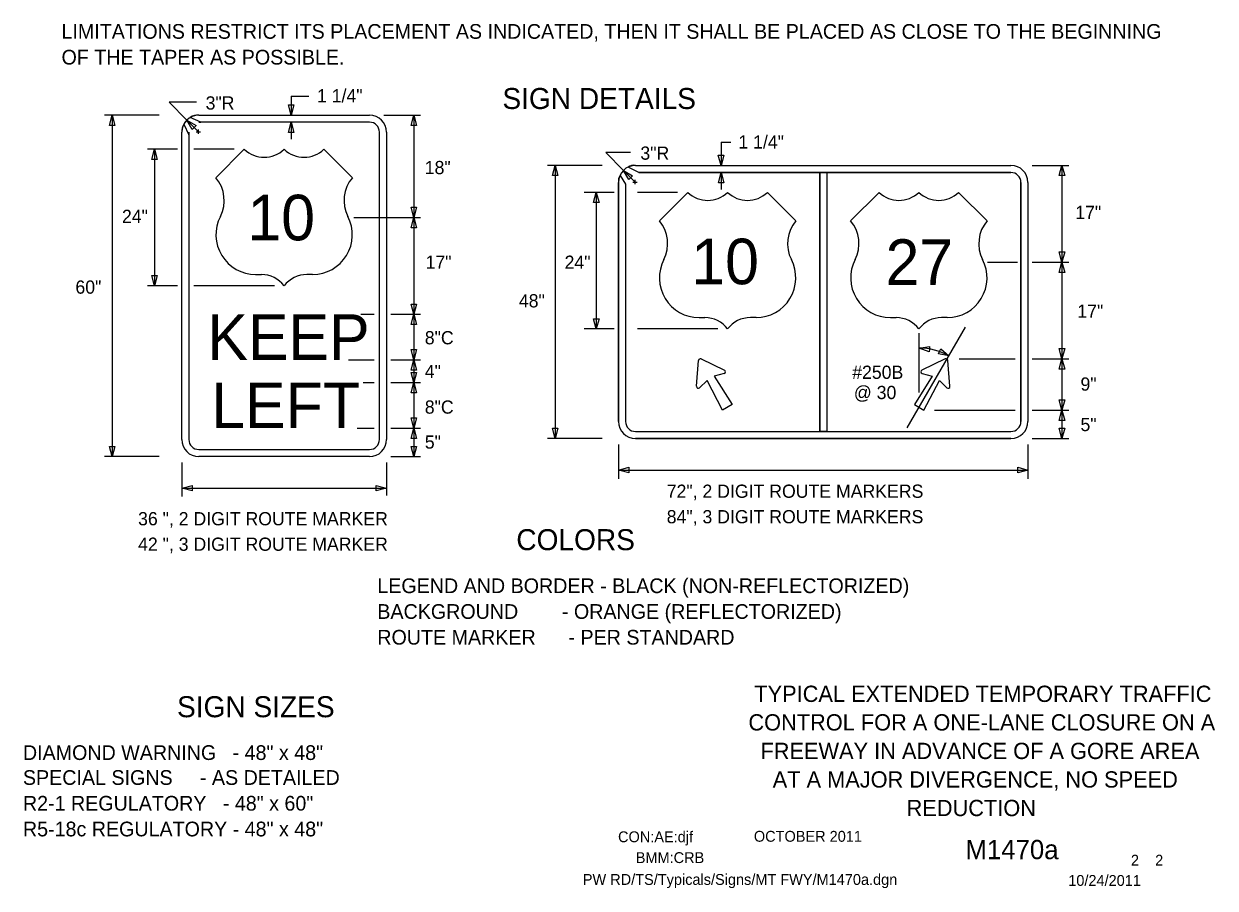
# Model space of a CAD drawing. Extents: x 16476 to 18475, y 6827 to 8243.
# Drawn here: x 17780 to 18461, y 7218 to 7712 of the extents above; entities that cross this region are included whole.
import ezdxf

# ---------------------------------------------------------------- set-up
doc = ezdxf.new("R2010")
doc.units = 0
for name, color, linetype in [('BORDER', 7, 'Continuous'), ('BORDER_SIGNAL_WO', 7, 'Continuous'), ('TRAFFIC_SIGNS_PR', 7, 'Continuous'), ('TYPICAL_EX', 7, 'Continuous'), ('TYPICAL_TEXT_DIMEN_PR', 7, 'Continuous')]:
    doc.layers.add(name, color=color, linetype=linetype)

msp = doc.modelspace()

# ---------------------------------------------------------------- linework, layer by layer
at = {"layer": 'BORDER'}
msp.add_line((17909.25, 7327.68), (17909.25, 7327.68), dxfattribs=at)
msp.add_line((17909.25, 7327.68), (17909.25, 7327.68), dxfattribs=at)
at = {"layer": 'TRAFFIC_SIGNS_PR'}
for p, q in [((17881.35, 7655.43), (17875.25, 7658.18)), ((17880.15, 7659.49), (17977.65, 7659.49)), ((17872.56, 7655.87), (17871.56, 7654.36)), ((17871.59, 7654.29), (17874.46, 7648.26)), ((17977.65, 7655.43), (17880.15, 7655.43)), ((17870.4, 7474.24), (17870.4, 7649.74)), ((17874.46, 7649.74), (17874.46, 7474.24)), ((17983.33, 7474.24), (17983.33, 7649.74)), ((17987.4, 7649.74), (17987.4, 7474.24)), ((18120.84, 7625.05), (18123.97, 7620.01)), ((18131.62, 7626.74), (18125.39, 7629.76)), ((18129.67, 7630.79), (18344.17, 7630.79)), ((18129.67, 7630.79), (18344.17, 7630.79)), ((18131.6, 7626.73), (18234.89, 7626.73)), ((18344.17, 7626.73), (18131.61, 7626.73)), ((18234.89, 7626.73), (18234.89, 7478.86)), ((18238.95, 7626.73), (18238.95, 7478.86)), ((18238.95, 7626.73), (18344.17, 7626.73)), ((18119.92, 7621.04), (18119.92, 7484.54)), ((18119.92, 7484.54), (18119.92, 7621.04)), ((18123.98, 7619.99), (18123.98, 7484.54)), ((18123.98, 7619.99), (18123.98, 7484.54)), ((18349.85, 7621.04), (18349.85, 7575.29)), ((18349.85, 7484.54), (18349.85, 7621.04)), ((18353.92, 7621.04), (18353.92, 7484.54)), ((18353.92, 7621.04), (18353.92, 7484.54)), ((18349.85, 7575.29), (18349.85, 7484.54)), ((18164.52, 7504.65), (18165.67, 7519.37)), ((18167.18, 7520.24), (18180.5, 7513.88)), ((18306.65, 7520.24), (18293.34, 7513.88)), ((18309.31, 7504.65), (18308.17, 7519.37)), ((18129.67, 7478.86), (18344.17, 7478.86)), ((18129.67, 7474.79), (18344.17, 7474.79)), ((18344.17, 7474.79), (18129.67, 7474.79)), ((17880.15, 7468.55), (17977.65, 7468.55)), ((17977.65, 7464.49), (17880.15, 7464.49))]:
    msp.add_line(p, q, dxfattribs=at)
for points in [[(18131.61, 7626.73), (18131.59, 7626.74)], [(18123.97, 7620.01), (18123.98, 7619.99)], [(18180.33, 7511.91), (18174.61, 7510.33), (18184.83, 7494.16), (18179.43, 7491.04), (18170.54, 7507.98), (18166.31, 7503.81)], [(18293.5, 7511.91), (18299.22, 7510.33), (18289.01, 7494.16), (18294.4, 7491.04), (18303.3, 7507.98), (18307.52, 7503.81)]]:
    msp.add_lwpolyline(points, dxfattribs=at)
msp.add_lwpolyline([(18234.89, 7626.73), (18238.95, 7626.73), (18238.95, 7478.86), (18234.89, 7478.86)], close=True, dxfattribs=at)
for centre, radius, start, end in [((17880.15, 7649.74), 9.75, 90, 180), ((17879.56, 7651.92), 7.6, 85.58319, 124.53531), ((17977.65, 7649.74), 9.75, 0, 90), ((17877.43, 7650.33), 7.06, 145.86811, 184.82317), ((17880.75, 7659.86), 4.47, 262.2432, 277.7568), ((17977.65, 7649.74), 5.69, 0, 90), ((17869, 7649), 5.51, 352.24294, 7.75653), ((18128.99, 7624.23), 6.6, 84.11162, 123.06374), ((18126.05, 7621.75), 6.17, 147.60925, 186.56283), ((18129.67, 7621.04), 9.75, 90, 180), ((18129.67, 7621.04), 9.75, 90, 180), ((18130.61, 7633.91), 7.24, 277.81035, 278.05403), ((18344.17, 7621.04), 9.75, 0, 90), ((18344.17, 7621.04), 9.75, 0, 90), ((18344.17, 7621.04), 5.69, 0, 89.99421), ((18344.17, 7621.04), 5.69, 0, 90), ((18166.73, 7519.28), 1.06, 64.48226, 175.51774), ((18307.11, 7519.28), 1.06, 4.48226, 115.51774), ((18180.04, 7512.92), 1.06, 285.9885, 64.48226), ((18293.79, 7512.92), 1.06, 115.51774, 254.0115), ((18165.57, 7504.57), 1.06, 175.51775, 314.01151), ((18308.26, 7504.57), 1.06, 225.98849, 4.48225), ((18129.67, 7484.54), 9.75, 180, 270), ((18129.67, 7484.54), 9.75, 180, 270), ((18129.67, 7484.54), 5.69, 180, 270), ((18129.67, 7484.54), 5.69, 180, 270), ((18344.17, 7484.54), 9.75, 270, 0), ((18344.17, 7484.54), 5.69, 270, 0), ((18344.17, 7484.54), 9.75, 270, 0), ((18344.17, 7484.54), 5.69, 270, 0), ((17880.15, 7474.24), 9.75, 180, 270), ((17880.15, 7474.24), 5.69, 180, 270), ((17977.65, 7474.24), 5.69, 270, 0), ((17977.65, 7474.24), 9.75, 270, 0)]:
    msp.add_arc(centre, radius, start, end, dxfattribs=at)
at = {"layer": 'TYPICAL_EX'}
for p, q in [((17889.9, 7623.74), (17906.15, 7639.99)), ((17967.9, 7623.74), (17951.65, 7639.99)), ((18143.28, 7599.13), (18159.53, 7615.38)), ((18221.28, 7599.13), (18205.03, 7615.38)), ((18252.56, 7599.13), (18268.81, 7615.38)), ((18330.56, 7599.13), (18314.31, 7615.38)), ((17912.62, 7568.45), (17915.87, 7568.45)), ((17945.17, 7568.45), (17941.92, 7568.45)), ((18166.01, 7543.84), (18169.26, 7543.84)), ((18198.55, 7543.84), (18195.3, 7543.84)), ((18275.28, 7543.84), (18278.53, 7543.84)), ((18307.83, 7543.84), (18304.58, 7543.84))]:
    msp.add_line(p, q, dxfattribs=at)
for centre, radius, start, end in [((17917.52, 7651.83), 16.42, 226.14041, 313.85958), ((17940.27, 7651.83), 16.42, 226.14042, 313.85959), ((17874.49, 7610.73), 20.16, 333.09768, 40.19361), ((17983.3, 7610.73), 20.16, 139.80639, 206.90233), ((18170.91, 7627.22), 16.42, 226.14041, 313.85958), ((18193.65, 7627.22), 16.42, 226.14042, 313.85959), ((18280.18, 7627.22), 16.42, 226.14041, 313.85958), ((18302.93, 7627.22), 16.42, 226.14042, 313.85959), ((17912.66, 7591.18), 22.73, 152.6698, 269.90132), ((17945.13, 7591.18), 22.73, 270.09868, 27.3302), ((18127.88, 7586.12), 20.16, 333.09768, 40.19361), ((18236.68, 7586.12), 20.16, 139.80639, 206.90233), ((18237.16, 7586.12), 20.16, 333.09768, 40.19361), ((18345.96, 7586.12), 20.16, 139.80639, 206.90233), ((18166.05, 7566.56), 22.73, 152.6698, 269.90132), ((18198.51, 7566.56), 22.73, 270.09868, 27.3302), ((18275.32, 7566.56), 22.73, 152.6698, 269.90132), ((18307.79, 7566.56), 22.73, 270.09868, 27.3302), ((17915.91, 7552.17), 16.28, 37.1038, 90.13853), ((17941.88, 7552.17), 16.28, 89.86147, 142.8962), ((18169.3, 7527.56), 16.28, 37.1038, 90.13853), ((18195.26, 7527.56), 16.28, 89.86147, 142.8962), ((18278.57, 7527.56), 16.28, 37.1038, 90.13853), ((18304.54, 7527.56), 16.28, 89.86147, 142.8962)]:
    msp.add_arc(centre, radius, start, end, dxfattribs=at)
at = {"layer": 'TYPICAL_TEXT_DIMEN_PR'}
for p, q in [((17878.76, 7666.78), (17863.11, 7666.78)), ((17863.11, 7666.78), (17873.35, 7656.54)), ((17932.87, 7659.49), (17931.3, 7665.35)), ((17931.3, 7665.35), (17932.87, 7665.35)), ((17932.87, 7670.25), (17932.87, 7659.49)), ((17932.87, 7670.25), (17942.97, 7670.25)), ((17932.87, 7665.35), (17934.44, 7665.35)), ((17934.44, 7665.35), (17932.87, 7659.49)), ((17857.57, 7659.49), (17826.27, 7659.49)), ((17829.04, 7653.63), (17830.61, 7659.49)), ((17830.61, 7659.49), (17830.61, 7464.49)), ((17830.61, 7659.49), (17832.18, 7653.63)), ((17985.94, 7659.49), (18006.9, 7659.49)), ((18001.43, 7653.63), (18003, 7659.49)), ((18003, 7659.49), (18003, 7600.99)), ((18003, 7659.49), (18004.57, 7653.63)), ((17830.61, 7653.63), (17829.04, 7653.63)), ((17832.18, 7653.63), (17830.61, 7653.63)), ((17873.35, 7656.54), (17879.9, 7649.98)), ((17876.38, 7651.28), (17873.35, 7656.54)), ((17873.35, 7656.54), (17878.6, 7653.51)), ((17877.49, 7652.39), (17876.38, 7651.28)), ((17878.6, 7653.51), (17877.49, 7652.39)), ((17931.35, 7649.57), (17932.92, 7655.43)), ((17932.92, 7655.43), (17932.92, 7645.68)), ((17932.92, 7655.43), (17934.49, 7649.57)), ((18003, 7653.63), (18001.43, 7653.63)), ((18004.57, 7653.63), (18003, 7653.63)), ((17878.7, 7649.98), (17881.11, 7649.98)), ((17879.9, 7648.77), (17879.9, 7651.19)), ((17932.92, 7649.57), (17931.35, 7649.57)), ((17934.49, 7649.57), (17932.92, 7649.57)), ((17868.02, 7639.99), (17850.9, 7639.99)), ((17853.22, 7634.13), (17854.79, 7639.99)), ((17854.79, 7639.99), (17854.79, 7561.99)), ((17854.79, 7639.99), (17856.36, 7634.13)), ((17900.26, 7639.99), (17877.39, 7639.99)), ((18126.81, 7638.08), (18112.63, 7638.08)), ((18112.63, 7638.08), (18122.78, 7627.93)), ((18178.53, 7643.94), (18178.53, 7630.79)), ((18178.53, 7643.94), (18184.05, 7643.94)), ((17854.79, 7634.13), (17853.22, 7634.13)), ((17856.36, 7634.13), (17854.79, 7634.13)), ((18178.53, 7630.79), (18176.95, 7636.65)), ((18176.95, 7636.65), (18178.53, 7636.65)), ((18178.53, 7636.65), (18180.1, 7636.65)), ((18180.1, 7636.65), (18178.53, 7630.79)), ((18110.69, 7630.79), (18079.39, 7630.79)), ((18082.16, 7624.93), (18083.73, 7630.79)), ((18083.73, 7624.93), (18082.16, 7624.93)), ((18083.73, 7630.79), (18083.73, 7474.79)), ((18083.73, 7630.79), (18085.3, 7624.93)), ((18085.3, 7624.93), (18083.73, 7624.93)), ((18122.78, 7627.93), (18129.43, 7621.28)), ((18125.81, 7622.67), (18122.78, 7627.93)), ((18122.78, 7627.93), (18128.04, 7624.9)), ((18128.04, 7624.9), (18126.93, 7623.78)), ((18177, 7620.87), (18178.57, 7626.73)), ((18177, 7620.87), (18178.57, 7626.73)), ((18178.57, 7626.73), (18178.57, 7616.98)), ((18178.57, 7626.73), (18180.15, 7620.87)), ((18178.57, 7626.73), (18180.15, 7620.87)), ((18356.29, 7630.79), (18377.25, 7630.79)), ((18371.78, 7624.93), (18373.35, 7630.79)), ((18373.35, 7624.93), (18371.78, 7624.93)), ((18373.35, 7630.79), (18373.35, 7575.54)), ((18373.35, 7630.79), (18374.92, 7624.93)), ((18374.92, 7624.93), (18373.35, 7624.93)), ((18126.93, 7623.78), (18125.81, 7622.67)), ((18128.22, 7621.28), (18130.64, 7621.28)), ((18129.43, 7620.07), (18129.43, 7622.49)), ((18178.57, 7620.87), (18177, 7620.87)), ((18178.57, 7620.87), (18177, 7620.87)), ((18180.15, 7620.87), (18178.57, 7620.87)), ((18180.15, 7620.87), (18178.57, 7620.87)), ((18117.55, 7615.38), (18100.42, 7615.38)), ((18105.71, 7609.52), (18107.28, 7615.38)), ((18107.28, 7615.38), (18107.28, 7537.38)), ((18107.28, 7615.38), (18108.86, 7609.52)), ((18153.65, 7615.38), (18130.77, 7615.38)), ((18003, 7600.99), (18001.43, 7606.85)), ((18001.43, 7606.85), (18003, 7606.85)), ((18003, 7606.85), (18004.57, 7606.85)), ((18004.57, 7606.85), (18003, 7600.99)), ((18107.28, 7609.52), (18105.71, 7609.52)), ((18108.86, 7609.52), (18107.28, 7609.52)), ((17968.79, 7600.99), (18006.9, 7600.99)), ((18001.43, 7595.13), (18003, 7600.99)), ((18003, 7600.99), (18003, 7545.74)), ((18003, 7600.99), (18004.57, 7595.13)), ((18003, 7595.13), (18001.43, 7595.13)), ((18004.57, 7595.13), (18003, 7595.13)), ((18373.35, 7575.54), (18371.78, 7581.4)), ((18371.78, 7581.4), (18373.35, 7581.4)), ((18373.35, 7581.4), (18374.92, 7581.4)), ((18374.92, 7581.4), (18373.35, 7575.54)), ((18330.73, 7575.54), (18347.88, 7575.54)), ((18356.29, 7575.54), (18377.25, 7575.54)), ((18371.78, 7569.68), (18373.35, 7575.54)), ((18373.35, 7569.68), (18371.78, 7569.68)), ((18373.35, 7575.54), (18373.35, 7520.29)), ((18373.35, 7575.54), (18374.92, 7569.68)), ((18374.92, 7569.68), (18373.35, 7569.68)), ((17854.79, 7561.99), (17853.22, 7567.85)), ((17853.22, 7567.85), (17854.79, 7567.85)), ((17854.79, 7567.85), (17856.36, 7567.85)), ((17856.36, 7567.85), (17854.79, 7561.99)), ((17868.02, 7561.99), (17850.9, 7561.99)), ((17923.39, 7561.99), (17877.39, 7561.99)), ((18003, 7545.74), (18001.43, 7551.6)), ((18001.43, 7551.6), (18003, 7551.6)), ((18003, 7551.6), (18004.57, 7551.6)), ((18004.57, 7551.6), (18003, 7545.74)), ((17972.72, 7545.74), (17980.4, 7545.74)), ((17989.77, 7545.74), (18006.9, 7545.74)), ((18001.43, 7539.88), (18003, 7545.74)), ((18003, 7545.74), (18003, 7519.74)), ((18003, 7545.74), (18004.57, 7539.88)), ((18107.28, 7537.38), (18105.71, 7543.24)), ((18105.71, 7543.24), (18107.28, 7543.24)), ((18107.28, 7543.24), (18108.86, 7543.24)), ((18108.86, 7543.24), (18107.28, 7537.38)), ((18003, 7539.88), (18001.43, 7539.88)), ((18004.57, 7539.88), (18003, 7539.88)), ((18117.55, 7537.38), (18100.42, 7537.38)), ((18176.77, 7537.38), (18130.77, 7537.38)), ((18284.95, 7480.89), (18318.19, 7538.48)), ((18291.71, 7501.05), (18291.71, 7535.04)), ((18003, 7519.74), (18001.43, 7525.6)), ((18001.43, 7525.6), (18003, 7525.6)), ((18003, 7525.6), (18004.57, 7525.6)), ((18004.57, 7525.6), (18003, 7519.74)), ((18291.74, 7526.49), (18297.73, 7527.45)), ((18297.4, 7524.32), (18291.74, 7526.49)), ((18297.57, 7525.88), (18297.4, 7524.32)), ((18297.73, 7527.45), (18297.57, 7525.88)), ((18302.72, 7523.16), (18303.4, 7524.58)), ((18308.69, 7522.03), (18302.72, 7523.16)), ((18303.4, 7524.58), (18304.09, 7525.99)), ((18304.09, 7525.99), (18308.69, 7522.03)), ((18373.35, 7520.29), (18371.78, 7526.15)), ((18371.78, 7526.15), (18373.35, 7526.15)), ((18373.35, 7526.15), (18374.92, 7526.15)), ((18374.92, 7526.15), (18373.35, 7520.29)), ((17965.71, 7519.74), (17980.4, 7519.74)), ((17989.77, 7519.74), (18006.9, 7519.74)), ((18001.43, 7513.88), (18003, 7519.74)), ((18003, 7519.74), (18003, 7506.74)), ((18003, 7519.74), (18004.57, 7513.88)), ((18314.66, 7520.29), (18346.53, 7520.29)), ((18356.29, 7520.29), (18377.25, 7520.29)), ((18371.78, 7514.43), (18373.35, 7520.29)), ((18373.35, 7520.29), (18373.35, 7491.04)), ((18373.35, 7520.29), (18374.92, 7514.43)), ((18003, 7513.88), (18001.43, 7513.88)), ((18003, 7506.74), (18001.43, 7512.6)), ((18001.43, 7512.6), (18003, 7512.6)), ((18004.57, 7513.88), (18003, 7513.88)), ((18003, 7512.6), (18004.57, 7512.6)), ((18004.57, 7512.6), (18003, 7506.74)), ((18373.35, 7514.43), (18371.78, 7514.43)), ((18374.92, 7514.43), (18373.35, 7514.43)), ((17974.06, 7506.74), (17980.4, 7506.74)), ((17989.77, 7506.74), (18006.9, 7506.74)), ((18001.43, 7500.88), (18003, 7506.74)), ((18003, 7506.74), (18003, 7480.74)), ((18003, 7506.74), (18004.57, 7500.88)), ((18003, 7500.88), (18001.43, 7500.88)), ((18004.57, 7500.88), (18003, 7500.88)), ((18373.35, 7491.04), (18371.78, 7496.9)), ((18371.78, 7496.9), (18373.35, 7496.9)), ((18373.35, 7496.9), (18374.92, 7496.9)), ((18374.92, 7496.9), (18373.35, 7491.04)), ((18300.52, 7491.04), (18346.53, 7491.04)), ((18356.29, 7491.04), (18377.25, 7491.04)), ((18371.78, 7485.18), (18373.35, 7491.04)), ((18373.35, 7491.04), (18373.35, 7474.79)), ((18373.35, 7491.04), (18374.92, 7485.18)), ((18003, 7480.74), (18001.43, 7486.6)), ((18001.43, 7486.6), (18003, 7486.6)), ((18003, 7486.6), (18004.57, 7486.6)), ((18004.57, 7486.6), (18003, 7480.74)), ((18373.35, 7485.18), (18371.78, 7485.18)), ((18374.92, 7485.18), (18373.35, 7485.18)), ((17970.56, 7480.74), (17980.4, 7480.74)), ((17989.77, 7480.74), (18006.9, 7480.74)), ((18001.43, 7474.88), (18003, 7480.74)), ((18003, 7474.88), (18001.43, 7474.88)), ((18003, 7480.74), (18003, 7464.49)), ((18003, 7480.74), (18004.57, 7474.88)), ((18004.57, 7474.88), (18003, 7474.88)), ((18110.69, 7474.79), (18079.39, 7474.79)), ((18083.73, 7474.79), (18082.16, 7480.65)), ((18082.16, 7480.65), (18083.73, 7480.65)), ((18083.73, 7480.65), (18085.3, 7480.65)), ((18085.3, 7480.65), (18083.73, 7474.79)), ((18356.29, 7474.79), (18373.42, 7474.79)), ((18356.29, 7474.79), (18377.25, 7474.79)), ((18356.29, 7474.79), (18373.42, 7474.79)), ((18373.35, 7474.79), (18371.78, 7480.65)), ((18371.78, 7480.65), (18373.35, 7480.65)), ((18373.35, 7480.65), (18374.92, 7480.65)), ((18374.92, 7480.65), (18373.35, 7474.79)), ((17830.61, 7464.49), (17829.04, 7470.35)), ((17829.04, 7470.35), (17830.61, 7470.35)), ((17830.61, 7470.35), (17832.18, 7470.35)), ((17832.18, 7470.35), (17830.61, 7464.49)), ((18003, 7464.49), (18001.43, 7470.35)), ((18001.43, 7470.35), (18003, 7470.35)), ((18003, 7470.35), (18004.57, 7470.35)), ((18004.57, 7470.35), (18003, 7464.49)), ((18119.92, 7471.45), (18119.92, 7451.89)), ((18353.92, 7471.45), (18353.92, 7451.89)), ((17857.57, 7464.49), (17826.27, 7464.49)), ((17870.4, 7461.15), (17870.4, 7441.8)), ((17987.4, 7461.15), (17987.4, 7442.25)), ((17989.77, 7464.49), (18006.9, 7464.49)), ((18119.92, 7456.82), (18125.78, 7458.39)), ((18119.92, 7456.82), (18353.92, 7456.82)), ((18125.78, 7455.25), (18119.92, 7456.82)), ((18125.78, 7458.39), (18125.78, 7456.82)), ((18125.78, 7456.82), (18125.78, 7455.25)), ((18348.06, 7456.82), (18348.06, 7458.39)), ((18348.06, 7458.39), (18353.92, 7456.82)), ((18353.92, 7456.82), (18348.06, 7455.25)), ((18348.06, 7455.25), (18348.06, 7456.82)), ((17870.4, 7446.52), (17876.26, 7448.09)), ((17876.26, 7448.09), (17876.26, 7446.52)), ((17981.53, 7446.52), (17981.53, 7448.09)), ((17981.53, 7448.09), (17987.4, 7446.52)), ((17870.4, 7446.52), (17987.4, 7446.52)), ((17876.26, 7444.95), (17870.4, 7446.52)), ((17876.26, 7446.52), (17876.26, 7444.95)), ((17987.4, 7446.52), (17981.53, 7444.95)), ((17981.53, 7444.95), (17981.53, 7446.52))]:
    msp.add_line(p, q, dxfattribs=at)
msp.add_arc((18291.9, 7492.05), 34.39, 60.74521, 90.32117, dxfattribs=at)

# ---------------------------------------------------------------- texts
at = {"layer": 'BORDER'}
for s, p in [('TYPICAL EXTENDED TEMPORARY TRAFFIC', (18197.55, 7324.41)), ('CONTROL FOR A ONE-LANE CLOSURE ON A', (18194.17, 7308.11)), ('FREEWAY IN ADVANCE OF A GORE AREA', (18201.06, 7291.81)), ('AT A MAJOR DIVERGENCE, NO SPEED', (18208.06, 7275.51)), ('REDUCTION', (18284.56, 7259.21))]:
    msp.add_text(s, height=9.3, dxfattribs=at).set_placement(p)
at = {"layer": 'BORDER_SIGNAL_WO'}
for s, height, p in [('CON:AE:djf  ', 6.2, (18119.69, 7244.31)), ('    OCTOBER 2011    ', 6.2, (18188.08, 7244.59)), ('    M1470a   ', 11, (18301.86, 7234.63)), ('BMM:CRB   ', 6.2, (18129.81, 7232.42)), (' 2    2 ', 6.2, (18410.45, 7230.95)), ('PW RD/TS/Typicals/Signs/MT FWY/M1470a.dgn      ', 6.2, (18099.55, 7219.96)), ('10/24/2011    ', 6.2, (18376.93, 7219.38))]:
    msp.add_text(s, height=height, dxfattribs=at).set_placement(p)
at = {"layer": 'TRAFFIC_SIGNS_PR'}
for s, p in [('10', (17907.87, 7587.99)), ('10', (18161.52, 7562.92)), ('27', (18272.52, 7562.56)), ('KEEP', (17885, 7519.74)), ('LEFT', (17887.23, 7480.74))]:
    msp.add_text(s, height=26, dxfattribs=at).set_placement(p)
at = {"layer": 'TYPICAL_TEXT_DIMEN_PR'}
for s, height, p in [('LIMITATIONS RESTRICT ITS PLACEMENT AS INDICATED, THEN IT SHALL BE PLACED AS CLOSE TO THE BEGINNING', 8.4, (17801.7, 7703.06)), ('OF THE TAPER AS POSSIBLE.', 8.4, (17801.7, 7688.36)), ('1 1/4"', 7.55, (17947.67, 7666.75)), ('SIGN DETAILS', 12, (18053.62, 7662.96)), ('3"R', 7.55, (17884.03, 7662.65)), ('1 1/4"', 7.55, (18188.45, 7640.37)), ('3"R', 7.55, (18132.45, 7634)), ('18"', 7.55, (18009.24, 7625.76)), ('24"', 7.55, (17836.24, 7597.88)), ('17"', 7.55, (18380.93, 7600.15)), ('17"', 7.55, (18009.69, 7571.71)), ('24"', 7.55, (18089.14, 7571.71)), ('60"', 7.55, (17809.64, 7557.51)), ('48"', 7.55, (18063.03, 7549.69)), ('17"', 7.55, (18382.13, 7543.79)), ('8"C', 7.55, (18009.27, 7528.6)), ('4" ', 7.55, (18009.27, 7509.34)), ('#250B', 7.55, (18253.48, 7508.88)), ('9"', 7.55, (18383.91, 7502.14)), ('@ 30', 7.55, (18254.42, 7497.33)), ('8"C', 7.55, (18009.27, 7489.01)), ('5"', 7.55, (18383.91, 7479.04)), ('5" ', 7.55, (18009.27, 7469.04)), ('72", 2 DIGIT ROUTE MARKERS', 7.55, (18147.5, 7440.96)), ('84", 3 DIGIT ROUTE MARKERS', 7.55, (18147.5, 7426.41)), ('36 ", 2 DIGIT ROUTE MARKER', 7.55, (17845.44, 7425.26)), ('COLORS', 12, (18061.56, 7411.07)), ('42 ", 3 DIGIT ROUTE MARKER', 7.55, (17845.44, 7410.71)), ('LEGEND AND BORDER - BLACK (NON-REFLECTORIZED)', 8.4, (17982.14, 7386.55)), ('BACKGROUND        - ORANGE (REFLECTORIZED)', 8.4, (17982.14, 7371.85)), ('ROUTE MARKER      - PER STANDARD', 8.4, (17982.14, 7357.15)), ('SIGN SIZES', 12, (17867.69, 7315.68)), ('DIAMOND WARNING   - 48" x 48"', 8.4, (17779.65, 7291.28)), ('SPECIAL SIGNS     - AS DETAILED', 8.4, (17779.65, 7277.06)), ('R2-1 REGULATORY   - 48" x 60"', 8.4, (17779.65, 7262.36)), ('R5-18c REGULATORY - 48" x 48"', 8.4, (17779.65, 7247.66))]:
    msp.add_text(s, height=height, dxfattribs=at).set_placement(p)

doc.saveas('drawing.dxf')
